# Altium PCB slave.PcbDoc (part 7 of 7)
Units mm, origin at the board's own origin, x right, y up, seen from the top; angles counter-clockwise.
Board outline 160 x 100 mm, 6 copper layers (Top, FUSED_VBAT-, Signals1, Signals2, SUPPLY, Bottom), stack 1.67 mm thick; 597 components, 381 nets, 1695 pads, 3028 vias.
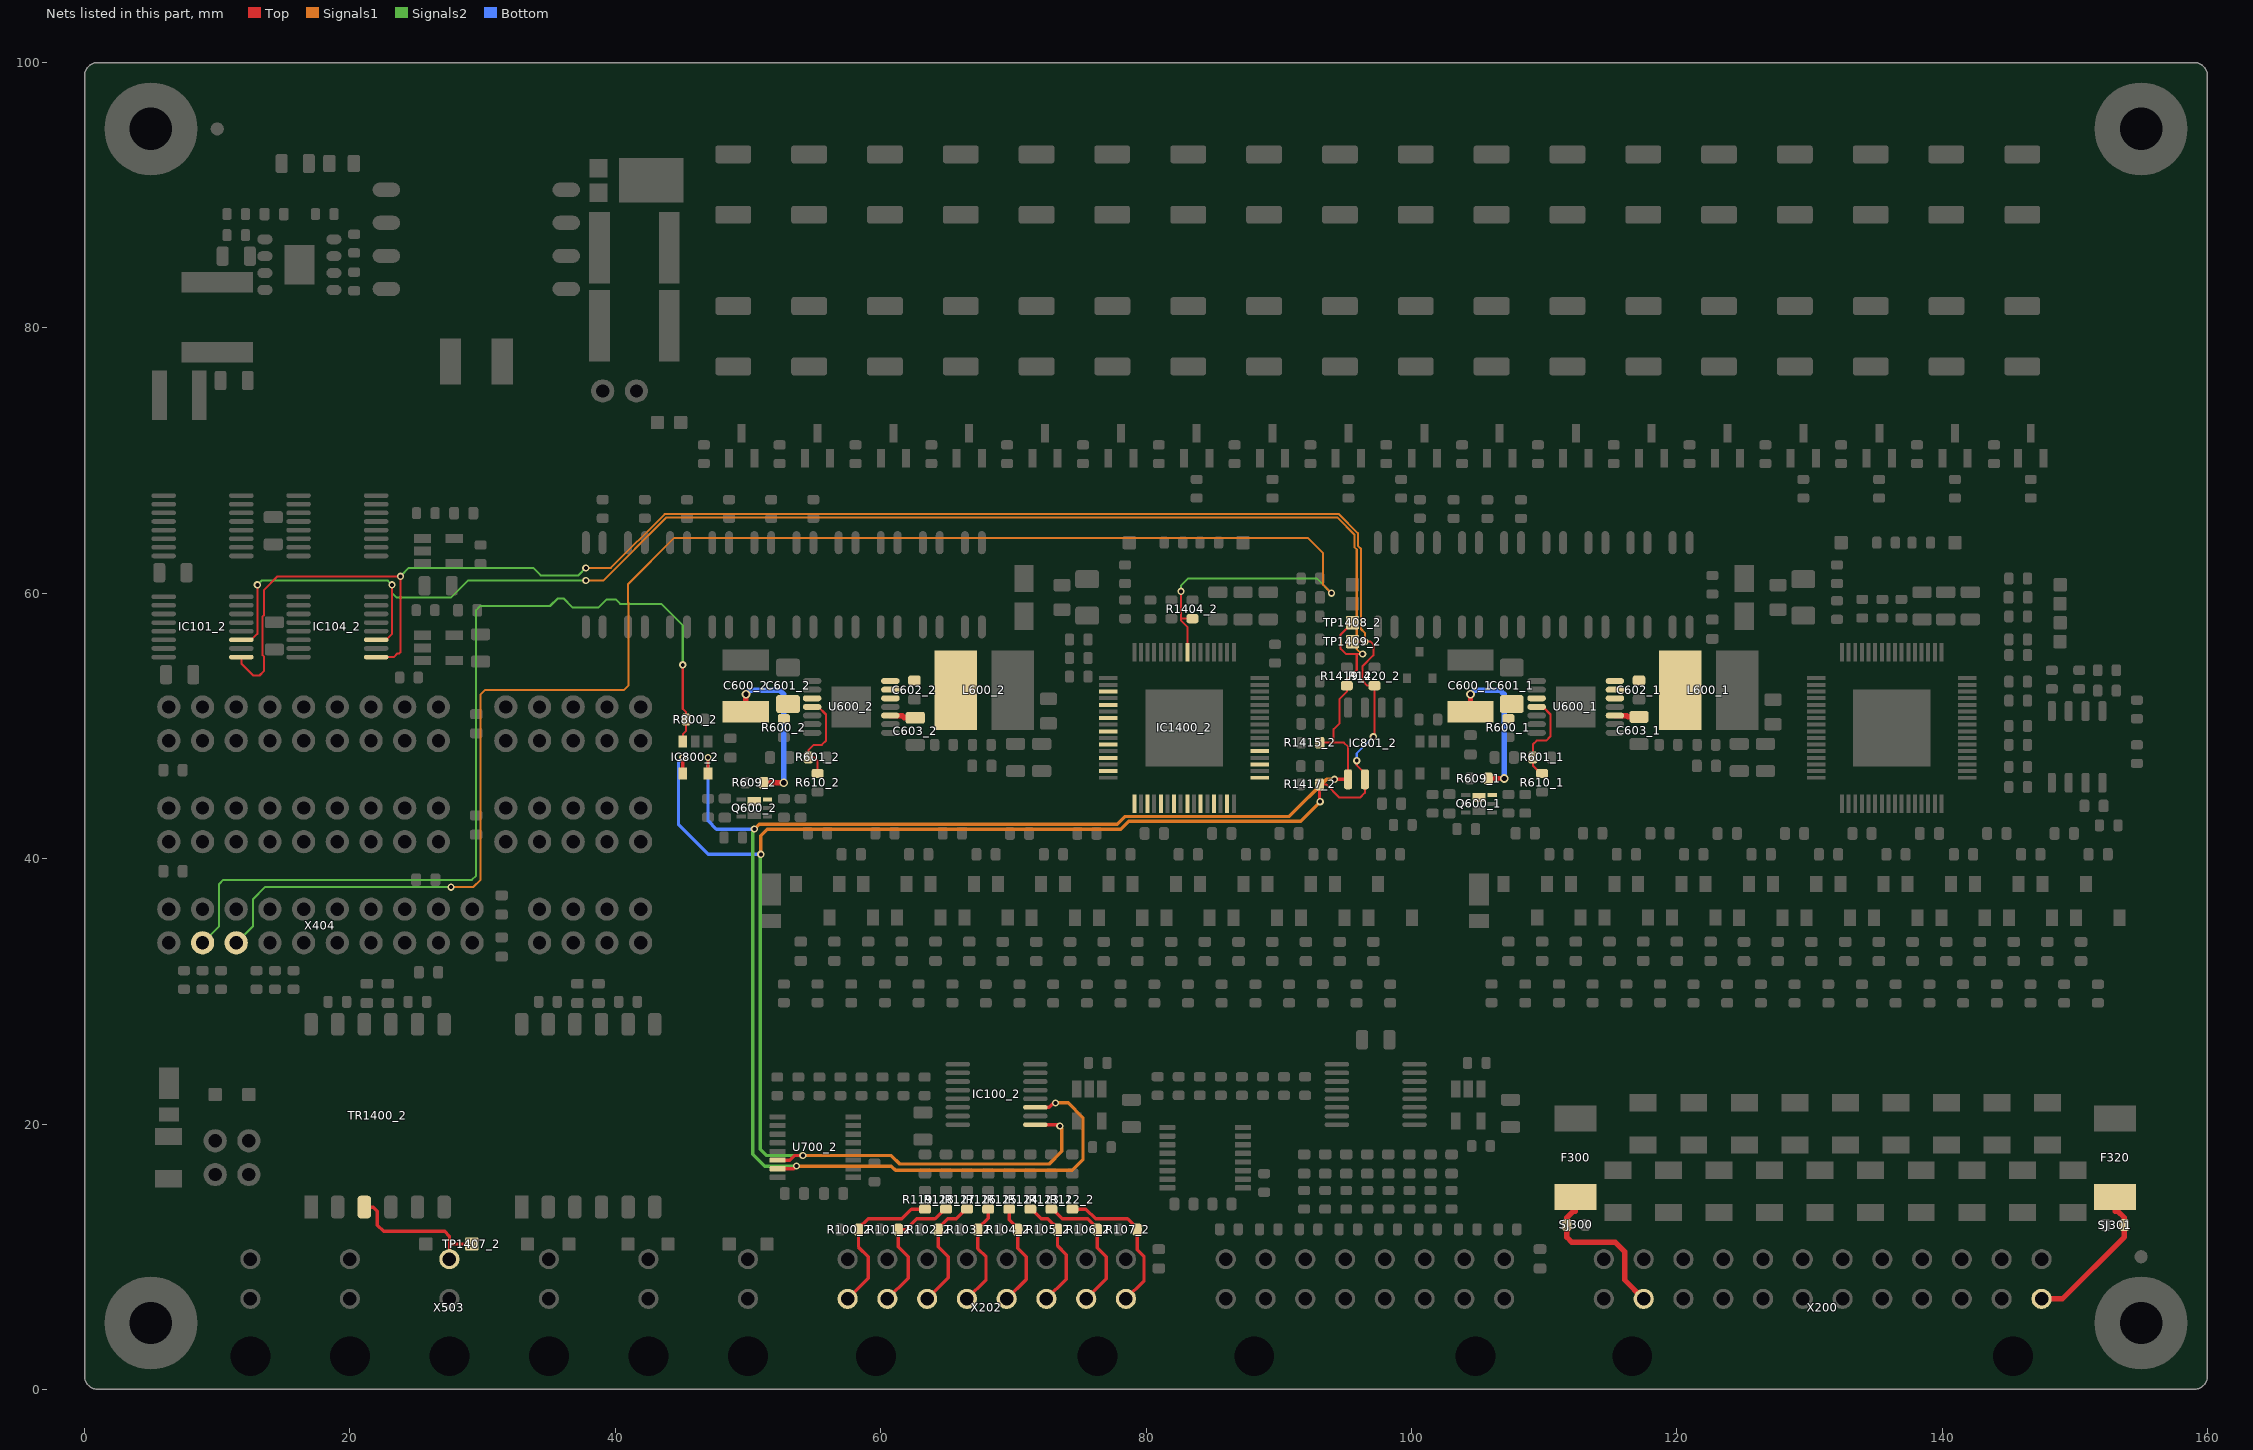
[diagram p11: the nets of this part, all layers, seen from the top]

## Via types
v1: diameter 0.55, hole 0.3, Top to Bottom, tented both sides, 2990 vias
v2: diameter 0.75, hole 0.5, Top to Bottom, tented both sides, 22 vias
v3: diameter 0.65, hole 0.4, Top to Bottom, tented both sides, 16 vias

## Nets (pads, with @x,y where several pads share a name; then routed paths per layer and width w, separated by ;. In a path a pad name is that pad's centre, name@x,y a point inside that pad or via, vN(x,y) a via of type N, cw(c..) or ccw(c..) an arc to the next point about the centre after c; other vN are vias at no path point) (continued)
SECONDARY-OUT-: TP1407_2.1 TR1400_2.3 X503.2 | length 11.4
  Top w0.254: TR1400_2.3@21.079,13.738 21.763,13.738 22.066,13.434 22.066,12.383 22.543,11.906 27.146,11.906 27.5,11.552 27.5,10.954 ; X503.2@27.5,9.815 27.5,10.954 ; TP1407_2.1@29.19,10.954 27.5,10.954
SECONDARY-S1: IC1400_2.37
SECONDARY-S2: IC1400_2.35
SECONDARY-S3: IC1400_2.33
SECONDARY-S4: IC1400_2.31
SECONDARY-S5: IC1400_2.29
SECONDARY-S6: IC1400_2.27
SECONDARY-S7: IC1400_2.25
SECONDARY-S8: IC1400_2.23
SECONDARY-S9: IC1400_2.21
SECONDARY-S10: IC1400_2.19
SECONDARY-S11: IC1400_2.17
SECONDARY-S12: IC1400_2.15
SECONDARY-S13: IC1400_2.13
SECONDARY-S14: IC1400_2.11
SECONDARY-S15: IC1400_2.9
SECONDARY-S16: IC1400_2.7
SECONDARY-S17: IC1400_2.5
SECONDARY-S18: IC1400_2.3
SECONDARY-SCL: IC100_2.1 IC101_2.1 IC104_2.1 IC800_2.4 IC801_2.6 R1417_2.1 R1420_2.1 TP1409_2.1 U700_2.14 | length 240.8
  Top w0.152: IC101_2.1@11.815,55.193 11.815,54.711 12.724,53.802 13.184,53.802 13.508,54.126 13.508,55.244 13.403,55.35 13.403,58.236 13.508,58.342 13.508,60.244 14.529,61.265 23.8,61.265 v1(23.812,61.277) 23.812,55.562 23.722,55.472 23.583,55.472 23.292,55.181 23.013,55.181 23.002,55.193 IC104_2.1@21.975,55.193 ; IC104_2.1@21.946,55.181 IC104_2.1@21.975,55.181 ; R1417_2.1@93.093,45.605 93.575,45.605 94.571,44.609 96.153,44.609 96.5,44.956 IC801_2.6@96.5,45.98 96.5,46.43 95.885,47.045 v1(95.885,47.38) ; R1417_2.1@93.129,45.548 R1417_2.1@93.143,45.561 ; TP1409_2.1@95.567,56.356 96.93,56.356 97.135,56.151 97.135,55.322 96.315,54.502 96.315,53.393 96.671,53.037 R1420_2.1@97.223,53.037 97.223,49.268 v1(97.135,49.18)
  Top w0.254: IC800_2.4@45.085,46.428 IC800_2.4@45.088,46.425 45.088,47.622 v1(45.085,47.625) ; U700_2.14@52.236,17.281 53.159,17.281 53.499,17.621 v1(54.134,17.621) ; IC100_2.1@71.664,19.95 73.395,19.95 v1(73.501,19.844) ; R1417_2.1@93.072,45.605 93.072,44.341 v1(93.122,44.291)
  Signals2 w0.152: v1(23.812,61.277) 24.447,61.912 33.823,61.912 34.378,61.358 37.228,61.358 v1(37.782,61.912)
  Signals2 w0.254: v1(50.97,40.322) 50.939,40.291 50.939,18.098 51.415,17.621 v1(54.134,17.621)
  Signals1 w0.152: v1(37.782,61.912) 39.671,61.912 43.718,65.959 94.545,65.959 95.966,64.539 95.966,63.588 96.203,63.351 96.203,57.309 96.5,57.011 v1(96.5,56.357)
  Signals1 w0.254: v1(50.97,40.322) 50.97,41.74 51.458,42.227 78.105,42.227 78.702,42.824 91.656,42.824 v1(93.122,44.291) ; v1(54.134,17.621) 60.801,17.621 61.436,16.986 72.707,16.986 73.66,17.939 73.66,19.685 v1(73.501,19.844)
  Bottom w0.152: v1(95.885,47.38) 95.885,47.942 97.122,49.18 v1(97.135,49.18)
  Bottom w0.254: v1(45.085,47.625) 44.767,47.307 44.767,42.545 46.99,40.322 v1(50.97,40.322)
SECONDARY-SDA: IC100_2.3 IC101_2.3 IC104_2.3 IC800_2.5 IC801_2.5 R1415_2.1 R1419_2.1 TP1408_2.1 U700_2.15 | length 238.5
  Top w0.152: IC101_2.3@11.786,56.502 IC101_2.3@11.815,56.502 ; IC101_2.3@11.815,56.493 12.565,56.493 13.018,56.945 v1(13.018,60.642) ; IC104_2.3@21.946,56.502 IC104_2.3@22.735,56.502 ; IC104_2.3@21.975,56.493 22.725,56.493 IC104_2.3@22.735,56.502 ; v1(23.177,60.642) 23.177,56.945 IC104_2.3@22.735,56.502 ; R1415_2.1@93.134,48.767 93.139,48.748 93.143,48.736 94.139,48.736 ; IC801_2.5@95.23,45.98 95.23,48.422 94.916,48.736 94.139,48.736 ; TP1408_2.1@95.567,57.785 94.675,56.892 94.675,55.82 95.068,55.427 95.885,55.427 ; v1(96.335,55.427) 95.885,55.427 ; 94.139,48.736 94.139,49.753 94.595,50.209 94.595,52.042 95.135,52.582 R1419_2.1@95.135,53.034 95.135,53.485 95.556,53.906 95.885,54.235 95.885,55.427
  Top w0.254: IC800_2.5@46.988,46.425 46.988,47.623 v1(46.99,47.625) ; U700_2.15@52.236,16.631 53.461,16.631 v1(53.657,16.828) ; IC100_2.3@71.664,21.25 72.69,21.25 73.03,21.59 v1(73.184,21.59) ; v1(94.212,45.98) IC801_2.5@95.23,45.98
  Signals2 w0.152: v1(13.018,60.642) 13.335,60.96 22.86,60.96 v1(23.177,60.642) 23.177,60.008 23.495,59.69 27.622,59.69 28.892,60.96 v1(37.782,60.96)
  Signals2 w0.254: v1(50.482,42.227) 50.365,42.11 50.365,17.719 51.256,16.828 v1(53.657,16.828)
  Signals1 w0.152: v1(37.782,60.96) 39.078,60.96 43.823,65.705 94.44,65.705 95.712,64.434 95.712,63.483 95.885,63.309 95.885,55.792 96.25,55.427 v1(96.335,55.427)
  Signals1 w0.254: v1(50.482,42.227) 50.838,42.583 51.458,42.583 77.826,42.583 78.422,43.18 90.805,43.18 93.605,45.98 v1(94.212,45.98) ; v1(53.657,16.828) 60.801,16.828 61.119,16.51 74.454,16.51 75.248,17.304 75.248,20.479 74.136,21.59 v1(73.184,21.59)
  Bottom w0.254: v1(46.99,47.625) 46.99,42.862 47.625,42.227 v1(50.482,42.227)
SECONDARY-T-SENSOR_0: R107_2.1 R112_2.2 X202.1 | length 11.6
  Top w0.254: R112_2.2@74.454,13.588 75.471,13.588 76.2,12.859 78.608,12.859 79.332,12.135 R107_2.1@79.332,12.035 79.332,10.521 79.851,10.001 79.851,8.179 X202.1@78.49,6.818
SECONDARY-T-SENSOR_1: R106_2.1 R113_2.2 X202.2 | length 10.3
  Top w0.254: R113_2.2@72.866,13.588 72.966,13.588 73.695,12.859 75.608,12.859 76.332,12.135 R106_2.1@76.332,12.035 76.332,10.663 76.994,10.001 76.994,8.319 X202.2@75.493,6.818
SECONDARY-T-SENSOR_2: R105_2.1 R114_2.2 X202.3 | length 8.9
  Top w0.254: R114_2.2@71.279,13.588 71.379,13.588 72.108,12.859 72.608,12.859 73.332,12.135 R105_2.1@73.332,12.035 73.332,10.806 73.977,10.16 73.977,8.299 X202.3@72.496,6.818
SECONDARY-T-SENSOR_3: R104_2.1 R115_2.2 X202.4 | length 7.9
  Top w0.254: X202.4@69.499,6.818 70.961,8.28 70.961,10.001 70.332,10.631 R104_2.1@70.332,12.035 70.332,12.135 69.691,12.775 R115_2.2@69.691,13.588
SECONDARY-T-SENSOR_4: R103_2.1 R116_2.2 X202.5 | length 7.9
  Top w0.254: X202.5@66.501,6.818 67.945,8.262 67.945,10.001 67.332,10.615 R103_2.1@67.332,12.035 67.332,12.135 68.104,12.907 R116_2.2@68.104,13.588
SECONDARY-T-SENSOR_5: R102_2.1 R117_2.2 X202.6 | length 9.1
  Top w0.254: X202.6@63.504,6.818 65.087,8.401 65.087,10.001 64.331,10.757 R102_2.1@64.331,12.035 64.331,12.135 65.055,12.859 65.687,12.859 66.416,13.588 R117_2.2@66.516,13.588
SECONDARY-T-SENSOR_6: R101_2.1 R118_2.2 X202.7 | length 10.4
  Top w0.254: X202.7@60.507,6.818 62.071,8.382 62.071,10.001 61.331,10.741 R101_2.1@61.331,12.035 61.883,12.035 62.706,12.859 64.1,12.859 64.829,13.588 R118_2.2@64.929,13.588
SECONDARY-T-SENSOR_7: R100_2.1 R119_2.2 X202.8 | length 11.9
  Top w0.254: X202.8@57.51,6.818 59.055,8.363 59.055,10.001 58.331,10.725 R100_2.1@58.331,12.035 58.331,12.135 59.055,12.859 61.595,12.859 62.324,13.588 R119_2.2@63.341,13.588
SECONDARY-TEMP-ALERT: IC800_2.3 R800_2.1 X404.18 | length 70.8
  Top w0.152: v1(45.085,54.61) 45.085,51.286 45.337,51.033 R800_2.1@45.337,50.482 45.337,49.627 45.088,49.377 IC800_2.3@45.088,48.825
  Signals2 w0.152: X404.18@8.89,33.655 10.14,34.905 10.14,38.088 10.457,38.405 29.19,38.405 29.507,38.723 29.507,58.725 29.825,59.043 35.081,59.043 35.648,59.609 36.107,59.609 36.771,58.945 38.752,58.945 39.353,59.546 40.022,59.546 40.369,59.199 43.476,59.199 45.085,57.59 v1(45.085,54.61)
SECONDARY-WDT: IC1400_2.56 R1404_2.1 X404.16 | length 130.3
  Top w0.152: v1(82.631,60.145) 82.631,58.102 ; IC1400_2.56@83.117,55.598 83.117,57.474 82.631,57.96 82.631,58.102 ; R1404_2.1@83.502,58.088 82.646,58.088 82.631,58.102
  Signals2 w0.152: X404.16@11.43,33.655 12.7,34.925 12.7,36.957 13.589,37.846 v1(27.618,37.846) ; v1(82.631,60.145) 82.631,60.565 83.185,61.119 92.869,61.119 v1(93.98,60.008)
  Signals1 w0.152: v1(27.618,37.846) 29.273,37.846 29.845,38.417 29.845,52.387 30.162,52.705 40.64,52.705 41.004,53.069 41.004,59.283 40.957,59.329 40.957,60.684 44.455,64.181 92.197,64.181 93.345,63.033 93.345,60.642 v1(93.98,60.008)
SHDN_1: R601_1.1 R610_1.1 U600_1.4 | length 7.1
  Top w0.152: U600_1.4@109.445,51.435 109.92,51.435 110.49,50.865 110.49,49.212 110.172,48.895 109.445,48.895 109.155,48.605 R601_1.1@109.155,47.625 109.155,47.02 109.755,46.42 R610_1.1@109.855,46.42
SHDN_2: R601_2.1 R610_2.1 U600_2.4 | length 7.2
  Top w0.152: U600_2.4@54.835,51.435 55.31,51.435 55.88,50.865 55.88,48.895 55.562,48.578 54.946,48.578 54.545,48.177 R601_2.1@54.545,47.625 54.997,47.625 55.245,47.377 R610_2.1@55.245,46.42
SW_1: C602_1.1 L600_1.1 U600_1.12 U600_1.13 U600_1.14
SW_2: C602_2.1 L600_2.1 U600_2.12 U600_2.13 U600_2.14
VBAT+: F300.1 SJ300.1 X200.11 | length 12.4
  Top w0.406: F300.1@112.375,14.5 112.375,13.418 112.187,13.418 111.715,12.947 SJ300.1@111.715,12.395 111.715,11.465 112.08,11.1 115.353,11.1 116.07,10.384 116.07,8.261 X200.11@117.513,6.818
VBAT-: F320.1 SJ301.2 X200.1 | length 11.6
  Top w0.406: X200.1@147.497,6.818 149.058,6.818 153.735,11.495 SJ301.2@153.735,12.383 153.735,12.934 153.238,13.431 153.035,13.431 F320.1@153.035,14.513
VCC_1: C603_1.2 U600_1.10 | length 1.9
  Top w0.406: U600_1.10@115.345,50.785 116.228,50.785 116.331,50.682 C603_1.2@117.157,50.682
VCC_2: C603_2.2 U600_2.10 | length 1.9
  Top w0.406: U600_2.10@60.735,50.785 61.618,50.785 61.784,50.619 C603_2.2@62.611,50.619
VIN_1: C600_1.2 C601_1.2 Q600_1.3 Q600_1.8 R600_1.2 R609_1.1 U600_1.3 | length 11.7
  Top w0.406: C600_1.2@104.457,51.073 v3(104.457,52.387) ; R609_1.1@105.793,46.038 v3(106.998,46.038)
  Bottom w0.406: v3(104.457,52.387) 104.775,52.705 106.68,52.705 106.998,52.387 v3(106.998,46.038)
VIN_2: C600_2.2 C601_2.2 Q600_2.3 Q600_2.8 R600_2.2 R609_2.1 U600_2.3 | length 12.6
  Top w0.406: C600_2.2@49.847,51.073 v3(49.847,52.387) ; R609_2.1@51.183,45.72 v3(52.705,45.72)
  Bottom w0.406: v3(49.847,52.387) 50.165,52.705 52.387,52.705 52.705,52.387 v3(52.705,45.72)
pads on no net: Designator5.Hole_3.2 Designator6.Hole_3.2 Designator7.Hole_3.2 Designator8.Hole_3.2 Designator11.0 Designator12.0 IC801_1.1 IC801_1.2 IC801_2.1 IC801_2.2 IC1400_1.53 IC1400_1.54 IC1400_2.53 IC1400_2.54 TR1400_1.2 TR1400_1.5 TR1400_2.2 TR1400_2.5 U700_1.13 U700_2.13 X200. X200.12 X200.23 X200.24 X201. X202. X500. X501. X502. X503. X1001. X1002.

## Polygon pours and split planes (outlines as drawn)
+5.0V_VREG_1 on SUPPLY "SUPPLY-+5.0V_VREG_1" (solid, pour order 811): 5.08,59.69 32.703,59.69 32.703,53.34 44.767,53.34 44.767,45.72 5.08,45.72
+5.0V_VREG_1 on SUPPLY "Polygon_1_Net_+5.0V_VREG_1" (solid, remove dead copper, pour order 222): 5.08,32.067 17.145,32.067 52.07,32.067 52.07,13.97 55.88,13.97 55.88,0 79.375,0 79.375,31.75 100.647,31.75 100.647,63.817 48.895,63.817 48.895,34.608 5.08,34.608
+5.0V_VREG_0 on SUPPLY "Polygon_1_Net_+5.0V_VREG_0" (solid, remove dead copper, pour order 223): 17 vertices, not listed, extent 5.08,-0.185 160.384,69.27
NetC900_2 on Top "Polygon_1_Net_N$74" (solid, remove dead copper, pour order 779): 10.795,76.835 10.795,72.866 7.938,72.866 7.937,76.835
NetC902_2 on Top "Polygon_1_Net_N$1254" (solid, remove dead copper, pour order 761): 21 vertices, not listed, extent 4.763,72.866 23.812,93.345
EXT_DC_IN- on Top "Polygon_1_Net_EXT_DC_IN-" (solid, remove dead copper, pour order 753): 14.922,83.502 14.922,89.218 17.399,89.218 17.399,79.692 28.575,79.692 28.575,75.248 11.271,75.247 11.271,77.152 7.144,77.152 7.144,80.804 13.018,80.804 13.018,83.502
FUSED_VBAT- on Top "Polygon_2_Net_FUSED_VBAT-" (solid, pour order 759): 39.688,88.9 39.688,73.66 30.48,73.66 30.48,79.375 34.925,79.375 34.925,83.82 38.1,83.82 38.1,88.9
EXT_DC_ISO+ on Top "Polygon_1_Net_EXT_DC_ISO+" (solid, pour order 755): 45.402,93.662 45.402,73.66 40.957,73.66 40.957,89.535 40.322,89.535 40.322,93.662
+5.0V_VREG_1 on Top "Top-+5.0V_VREG_1" (solid, pour order 797): 67.945,55.88 67.945,46.355 68.897,46.355 68.897,49.53 70.802,49.53 70.802,51.435 73.66,51.435 73.66,55.88
EXT_DC_ISO+ on Top "Top-EXT_DC_ISO+ 1" (solid, pour order 821): 46.37,45.085 49.212,45.085 49.212,46.355 50.165,46.355 50.165,45.085 49.847,45.085 49.847,44.133 46.37,44.133
VIN_2 on Top "Top-VIN_2" (solid, pour order 823): 49.939,44.767 50.482,44.767 50.482,46.355 52.07,46.355 52.07,44.132 51.117,44.133 51.117,43.815 49.939,43.815
VIN_2 on Top "Top-EXT_DC_ISO+" (solid, pour order 789): 47.625,52.387 55.562,52.387 55.562,51.752 53.657,51.752 53.657,50.165 47.625,50.165
FUSED_VBAT- on Top "Top-FUSED_VBAT-" (solid, pour order 787): 18 vertices, not listed, extent 47.625,44.767 73.025,55.88
EXT_DC_ISO+ on Top "Top-EXT_DC_ISO+ 2" (solid, pour order 819): 100.98,45.402 103.822,45.402 103.822,46.672 104.775,46.672 104.775,45.402 104.457,45.402 104.457,44.45 100.98,44.45
VIN_1 on Top "Top-VIN_1" (solid, pour order 817): 104.549,45.085 105.093,45.085 105.093,46.672 106.68,46.672 106.68,44.45 105.727,44.45 105.727,44.133 104.549,44.133
VIN_1 on Top "Top-EXT_DC_ISO+" (solid, pour order 799): 102.235,52.388 110.172,52.387 110.172,51.752 108.267,51.752 108.267,50.165 102.235,50.165 102.235,51.752
FUSED_VBAT- on Top "Top-FUSED_VBAT-" (solid, pour order 807): 18 vertices, not listed, extent 102.235,44.767 127.635,55.88
NetC605_1_2 on Top "Top-NetC1505_2_2" (solid, pour order 803): 124.46,49.212 125.73,49.212 125.73,50.8 128.27,50.8 128.27,48.26 124.46,48.26
+5.0V_VREG_0 on Top "Top-+5.0V_VREG_1" (solid, pour order 801): 122.555,55.88 122.555,46.355 123.507,46.355 123.507,49.53 125.412,49.53 125.412,51.435 128.27,51.435 128.27,55.88
SW_2 on Top "Top-SW_2" (solid, pour order 815): 60.008,53.975 63.817,53.975 63.817,55.88 66.675,55.88 66.675,49.53 63.817,49.53 63.817,52.705 61.595,52.705 61.595,51.752 60.008,51.752
SW_1 on Top "Top-SW_2" (solid, pour order 805): 114.617,53.975 118.427,53.975 118.427,55.88 121.285,55.88 121.285,49.53 118.427,49.53 118.427,52.705 116.205,52.705 116.205,51.752 114.617,51.752
CELL_FEEDBACK.CELL17_FEEDBACK+ on Top "Polygon_1_Net_CELL0_FEEDBACK+" (solid, pour order 417): 51.435,71.755 46.355,71.755 46.355,78.74 51.435,78.74
NetC605_2_2 on Top "Top-NetC1505_2_2" (solid, pour order 793): 69.85,49.212 71.12,49.212 71.12,50.8 73.66,50.8 73.66,48.26 69.85,48.26
NetIC900_5 on Top "Polygon_1_Net_N$80" (solid, remove dead copper, pour order 763): 26.352,81.597 26.352,93.345 19.685,93.345 19.685,91.44 24.447,91.44 24.447,86.36 21.59,86.36 21.59,83.502 18.098,83.502 18.097,81.597
NetD901_2 on Top "Polygon_1_Net_N$84" (solid, remove dead copper, pour order 757): 39.37,93.662 39.37,89.535 34.925,89.535 34.925,93.662
NetC905_1 on Top "Polygon_1_Net_N$92" (solid, remove dead copper, pour order 751): 16.192,93.345 16.192,91.44 19.05,91.44 19.05,93.345
NetTR900_6 on Top "Polygon_1_Net_N$74" (solid, remove dead copper, pour order 745): 37.465,88.9 37.465,84.455 34.925,84.455 34.925,88.9
CELL_FEEDBACK.CELL0_FEEDBACK+ on Top "Polygon_1_Net_FUSED_CELL_0-" (solid, pour order 193): 148.59,91.44 143.51,91.44 143.51,98.425 148.59,98.425
FUSED_CELL.CELL_12+ on Top "Polygon_1_Net_N$4" (solid, pour order 375): 74.295,90.17 74.295,80.01 69.215,80.01 69.215,90.17
CELL_FEEDBACK.CELL1_FEEDBACK+ on Top "Polygon_1_Net_CELL0_FEEDBACK+" (solid, pour order 385): 142.875,71.755 137.795,71.755 137.795,78.74 142.875,78.74
CELL_FEEDBACK.CELL0_FEEDBACK+ on Top "Polygon_1_Net_CELL0_FEEDBACK+" (solid, pour order 185): 148.59,71.755 143.51,71.755 143.51,78.74 148.59,78.74
CELL_FEEDBACK.CELL16_FEEDBACK+ on Top "Polygon_1_Net_CELL0_FEEDBACK+" (solid, pour order 415): 57.15,71.755 52.07,71.755 52.07,78.74 57.15,78.74
FUSED_CELL.CELL_0- on Top "Polygon_1_Net_N$4" (solid, pour order 214): 148.59,90.17 148.59,80.01 143.51,80.01 143.51,90.17
CELL_FEEDBACK.CELL13_FEEDBACK+ on Top "Polygon_1_Net_CELL0_FEEDBACK+" (solid, pour order 409): 74.295,71.755 69.215,71.755 69.215,78.74 74.295,78.74
CELL_FEEDBACK.CELL14_FEEDBACK+ on Top "Polygon_1_Net_CELL0_FEEDBACK+" (solid, pour order 411): 68.58,71.755 63.5,71.755 63.5,78.74 68.58,78.74
CELL_FEEDBACK.CELL12_FEEDBACK+ on Top "Polygon_1_Net_CELL0_FEEDBACK+" (solid, pour order 407): 80.01,71.755 74.93,71.755 74.93,78.74 80.01,78.74
CELL_FEEDBACK.CELL11_FEEDBACK+ on Top "Polygon_1_Net_CELL0_FEEDBACK+" (solid, pour order 405): 85.725,71.755 80.645,71.755 80.645,78.74 85.725,78.74
CELL_FEEDBACK.CELL9_FEEDBACK+ on Top "Polygon_1_Net_CELL0_FEEDBACK+" (solid, pour order 401): 97.155,71.755 92.075,71.755 92.075,78.74 97.155,78.74
CELL_FEEDBACK.CELL8_FEEDBACK+ on Top "Polygon_1_Net_CELL0_FEEDBACK+" (solid, pour order 399): 102.873,71.755 97.793,71.755 97.793,78.74 102.873,78.74
CELL_FEEDBACK.CELL7_FEEDBACK+ on Top "Polygon_1_Net_CELL0_FEEDBACK+" (solid, pour order 397): 108.585,71.755 103.505,71.755 103.505,78.74 108.585,78.74
CELL_FEEDBACK.CELL6_FEEDBACK+ on Top "Polygon_1_Net_CELL0_FEEDBACK+" (solid, pour order 395): 114.303,71.755 109.223,71.755 109.223,78.74 114.303,78.74
CELL_FEEDBACK.CELL5_FEEDBACK+ on Top "Polygon_1_Net_CELL0_FEEDBACK+" (solid, pour order 393): 120.015,71.755 114.935,71.755 114.935,78.74 120.015,78.74
CELL_FEEDBACK.CELL4_FEEDBACK+ on Top "Polygon_1_Net_CELL0_FEEDBACK+" (solid, pour order 391): 125.73,71.755 120.65,71.755 120.65,78.74 125.73,78.74
CELL_FEEDBACK.CELL3_FEEDBACK+ on Top "Polygon_1_Net_CELL0_FEEDBACK+" (solid, pour order 389): 131.445,71.755 126.365,71.755 126.365,78.74 131.445,78.74
CELL_FEEDBACK.CELL2_FEEDBACK+ on Top "Polygon_1_Net_CELL0_FEEDBACK+" (solid, pour order 387): 137.16,71.755 132.08,71.755 132.08,78.74 137.16,78.74
CELL_FEEDBACK.CELL15_FEEDBACK+ on Top "Polygon_1_Net_CELL0_FEEDBACK+" (solid, pour order 413): 62.865,71.755 57.785,71.755 57.785,78.74 62.865,78.74
CELL_FEEDBACK.CELL10_FEEDBACK+ on Top "Polygon_1_Net_CELL0_FEEDBACK+" (solid, pour order 403): 91.44,71.755 86.36,71.755 86.36,78.74 91.44,78.74
FUSED_CELL.CELL_16+ on Top "Polygon_1_Net_N$4" (solid, pour order 383): 51.435,90.17 51.435,80.01 46.355,80.01 46.355,90.17
FUSED_CELL.CELL_15+ on Top "Polygon_1_Net_N$4" (solid, pour order 381): 57.15,90.17 57.15,80.01 52.07,80.01 52.07,90.17
FUSED_CELL.CELL_14+ on Top "Polygon_1_Net_N$4" (solid, pour order 379): 62.865,90.17 62.865,80.01 57.785,80.01 57.785,90.17
FUSED_CELL.CELL_13+ on Top "Polygon_1_Net_N$4" (solid, pour order 377): 68.58,90.17 68.58,80.01 63.5,80.01 63.5,90.17
FUSED_CELL.CELL_11+ on Top "Polygon_1_Net_N$4" (solid, pour order 373): 80.01,90.17 80.01,80.01 74.93,80.01 74.93,90.17
FUSED_CELL.CELL_10+ on Top "Polygon_1_Net_N$4" (solid, pour order 371): 85.725,90.17 85.725,80.01 80.645,80.01 80.645,90.17
FUSED_CELL.CELL_9+ on Top "Polygon_1_Net_N$4" (solid, pour order 369): 91.44,90.17 91.44,80.01 86.36,80.01 86.36,90.17
FUSED_CELL.CELL_8+ on Top "Polygon_1_Net_N$4" (solid, pour order 367): 97.155,90.17 97.155,80.01 92.075,80.01 92.075,90.17
FUSED_CELL.CELL_7+ on Top "Polygon_1_Net_N$4" (solid, pour order 365): 102.87,90.17 102.87,80.01 97.79,80.01 97.79,90.17
FUSED_CELL.CELL_6+ on Top "Polygon_1_Net_N$4" (solid, pour order 363): 108.585,90.17 108.585,80.01 103.505,80.01 103.505,90.17
FUSED_CELL.CELL_5+ on Top "Polygon_1_Net_N$4" (solid, pour order 361): 114.303,90.17 114.303,80.01 109.223,80.01 109.223,90.17
FUSED_CELL.CELL_4+ on Top "Polygon_1_Net_N$4" (solid, pour order 359): 120.015,90.17 120.015,80.01 114.935,80.01 114.935,90.17
FUSED_CELL.CELL_3+ on Top "Polygon_1_Net_N$4" (solid, pour order 357): 125.73,90.17 125.73,80.01 120.65,80.01 120.65,90.17
FUSED_CELL.CELL_2+ on Top "Polygon_1_Net_N$4" (solid, pour order 355): 131.445,90.17 131.445,80.01 126.365,80.01 126.365,90.17
FUSED_CELL.CELL_1+ on Top "Polygon_1_Net_N$4" (solid, pour order 353): 137.16,90.17 137.16,80.01 132.08,80.01 132.08,90.17
FUSED_CELL.CELL_0+ on Top "Polygon_1_Net_N$4" (solid, pour order 351): 142.875,90.17 142.875,80.01 137.795,80.01 137.795,90.17
CELL_FEEDBACK.CELL17_FEEDBACK+ on Top "Polygon_1_Net_FUSED_CELL_0-" (solid, pour order 349): 51.435,91.44 46.355,91.44 46.355,98.425 51.435,98.425
CELL_FEEDBACK.CELL16_FEEDBACK+ on Top "Polygon_1_Net_FUSED_CELL_0-" (solid, pour order 347): 57.15,91.44 52.07,91.44 52.07,98.425 57.15,98.425
CELL_FEEDBACK.CELL15_FEEDBACK+ on Top "Polygon_1_Net_FUSED_CELL_0-" (solid, pour order 345): 62.865,91.44 57.785,91.44 57.785,98.425 62.865,98.425
CELL_FEEDBACK.CELL14_FEEDBACK+ on Top "Polygon_1_Net_FUSED_CELL_0-" (solid, pour order 343): 68.58,91.44 63.5,91.44 63.5,98.425 68.58,98.425
CELL_FEEDBACK.CELL13_FEEDBACK+ on Top "Polygon_1_Net_FUSED_CELL_0-" (solid, pour order 341): 74.295,91.44 69.215,91.44 69.215,98.425 74.295,98.425
CELL_FEEDBACK.CELL12_FEEDBACK+ on Top "Polygon_1_Net_FUSED_CELL_0-" (solid, pour order 339): 80.01,91.44 74.93,91.44 74.93,98.425 80.01,98.425
CELL_FEEDBACK.CELL11_FEEDBACK+ on Top "Polygon_1_Net_FUSED_CELL_0-" (solid, pour order 337): 85.725,91.44 80.645,91.44 80.645,98.425 85.725,98.425
CELL_FEEDBACK.CELL10_FEEDBACK+ on Top "Polygon_1_Net_FUSED_CELL_0-" (solid, pour order 335): 91.44,91.44 86.36,91.44 86.36,98.425 91.44,98.425
CELL_FEEDBACK.CELL9_FEEDBACK+ on Top "Polygon_1_Net_FUSED_CELL_0-" (solid, pour order 333): 97.155,91.44 92.075,91.44 92.075,98.425 97.155,98.425
CELL_FEEDBACK.CELL8_FEEDBACK+ on Top "Polygon_1_Net_FUSED_CELL_0-" (solid, pour order 331): 102.87,91.44 97.79,91.44 97.79,98.425 102.87,98.425
CELL_FEEDBACK.CELL7_FEEDBACK+ on Top "Polygon_1_Net_FUSED_CELL_0-" (solid, pour order 329): 108.585,91.44 103.505,91.44 103.505,98.425 108.585,98.425
CELL_FEEDBACK.CELL6_FEEDBACK+ on Top "Polygon_1_Net_FUSED_CELL_0-" (solid, pour order 327): 114.3,91.44 109.22,91.44 109.22,98.425 114.3,98.425
CELL_FEEDBACK.CELL5_FEEDBACK+ on Top "Polygon_1_Net_FUSED_CELL_0-" (solid, pour order 325): 120.015,91.44 114.935,91.44 114.935,98.425 120.015,98.425
CELL_FEEDBACK.CELL4_FEEDBACK+ on Top "Polygon_1_Net_FUSED_CELL_0-" (solid, pour order 323): 125.73,91.44 120.65,91.44 120.65,98.425 125.73,98.425
CELL_FEEDBACK.CELL3_FEEDBACK+ on Top "Polygon_1_Net_FUSED_CELL_0-" (solid, pour order 321): 131.445,91.44 126.365,91.44 126.365,98.425 131.445,98.425
CELL_FEEDBACK.CELL2_FEEDBACK+ on Top "Polygon_1_Net_FUSED_CELL_0-" (solid, pour order 319): 137.16,91.44 132.08,91.44 132.08,98.425 137.16,98.425
CELL_FEEDBACK.CELL1_FEEDBACK+ on Top "Polygon_1_Net_FUSED_CELL_0-" (solid, pour order 317): 142.875,91.44 137.795,91.44 137.795,98.425 142.875,98.425
no net on Top Overlay "Polygon_1_NoNet" (solid): 159.385,58.737 152.4,58.738 152.4,80.486 159.385,80.486
no net on Top Overlay "Polygon_22_NoNet" (solid): 105 vertices, not listed, extent 23.444,67.792 40.588,73.328
no net on Top Overlay "Polygon_23_NoNet" (solid): 75 vertices, not listed, extent 36.787,69.287 38.535,71.841
no net on Top Overlay "Polygon_24_NoNet" (solid): 33 vertices, not listed, extent 34.064,69.294 36.283,71.835
no net on Top Overlay "Polygon_25_NoNet" (solid): 69 vertices, not listed, extent 31.768,69.308 33.548,71.82
no net on Top Overlay "Polygon_26_NoNet" (solid): 53 vertices, not listed, extent 28.694,69.284 30.924,71.507
no net on Top Overlay "Polygon_27_NoNet" (solid): 60 vertices, not listed, extent 26.681,69.28 28.703,71.507
no net on Top Overlay "Polygon_28_NoNet" (solid): 61 vertices, not listed, extent 24.709,68.508 26.937,72.326
no net on Top Overlay "Polygon_42_NoNet" (solid): 33 vertices, not listed, extent 1.338,53.42 1.87,53.948
no net on Top Overlay "Polygon_41_NoNet" (solid): 17 vertices, not listed, extent 1.941,53.184 3.698,54.184
no net on Top Overlay "Polygon_40_NoNet" (solid): 133 vertices, not listed, extent 0.698,51.865 4.337,55.503
no net on Top Overlay "Polygon_39_NoNet" (solid): 59 vertices, not listed, extent 1.945,49.506 3.092,50.55
no net on Top Overlay "Polygon_38_NoNet" (solid): 58 vertices, not listed, extent 1.945,48.461 3.092,49.505
no net on Top Overlay "Polygon_37_NoNet" (solid): 134 vertices, not listed, extent 0.7,47.684 4.337,51.322
FUSED_VBAT- on Bottom "Polygon_2_Net_FUSED_VBAT-" (solid, remove dead copper, pour order 279): 75.248,42.227 75.248,57.468 90.487,57.468 90.487,42.227
FUSED_VBAT- on Bottom "Polygon_3_Net_FUSED_VBAT-" (solid, remove dead copper, pour order 278): 128.588,42.227 128.588,57.468 143.827,57.468 143.827,42.227
EXT_DC_IN- on Bottom "Polygon_2_Net_EXT_DC_IN-" (solid, pour order 773): 26.352,75.248 26.352,93.345 14.287,93.345 14.287,91.122 6.35,91.123 6.35,87.312 4.763,87.312 4.763,75.248
EXT_DC_ISO+ on Bottom "Polygon_6_Net_EXT_DC_ISO+" (solid, remove dead copper, pour order 771): 45.402,93.662 45.402,73.66 40.957,73.66 40.957,89.217 40.005,89.218 40.005,93.662
FUSED_VBAT- on Bottom "Polygon_3_Net_FUSED_VBAT-" (solid, pour order 769): 39.687,88.9 39.687,73.66 30.48,73.66 30.48,79.375 34.925,79.375 34.925,83.82 37.889,83.82 37.889,88.9
NetD901_2 on Bottom "Polygon_2_Net_N$84" (solid, pour order 767): 39.688,93.662 39.688,89.218 34.925,89.217 34.925,93.662
NetTR900_6 on Bottom "Polygon_2_Net_N$74" (solid, pour order 765): 37.465,88.9 37.465,84.455 34.925,84.455 34.925,88.9
CELL_FEEDBACK.CELL0_FEEDBACK+ on Bottom "Polygon_1_Net_FUSED_CELL_0-" (solid, pour order 739): 148.59,91.44 143.51,91.44 143.51,98.425 148.59,98.425
FUSED_CELL.CELL_12+ on Bottom "Polygon_1_Net_N$4" (solid, pour order 679): 74.295,90.17 74.295,80.01 69.215,80.01 69.215,90.17
FUSED_CELL.CELL_0- on Bottom "Polygon_1_Net_N$4" (solid, pour order 741): 148.59,90.17 148.59,80.01 143.51,80.01 143.51,90.17
CELL_FEEDBACK.CELL0_FEEDBACK+ on Bottom "Polygon_1_Net_CELL0_FEEDBACK+" (solid, pour order 743): 148.59,71.755 143.51,71.755 143.51,78.74 148.59,78.74
CELL_FEEDBACK.CELL1_FEEDBACK+ on Bottom "Polygon_1_Net_FUSED_CELL_0-" (solid, pour order 737): 142.875,91.44 137.795,91.44 137.795,98.425 142.875,98.425
CELL_FEEDBACK.CELL2_FEEDBACK+ on Bottom "Polygon_1_Net_FUSED_CELL_0-" (solid, pour order 735): 137.16,91.44 132.08,91.44 132.08,98.425 137.16,98.425
CELL_FEEDBACK.CELL3_FEEDBACK+ on Bottom "Polygon_1_Net_FUSED_CELL_0-" (solid, pour order 733): 131.445,91.44 126.365,91.44 126.365,98.425 131.445,98.425
CELL_FEEDBACK.CELL4_FEEDBACK+ on Bottom "Polygon_1_Net_FUSED_CELL_0-" (solid, pour order 731): 125.73,91.44 120.65,91.44 120.65,98.425 125.73,98.425
CELL_FEEDBACK.CELL5_FEEDBACK+ on Bottom "Polygon_1_Net_FUSED_CELL_0-" (solid, pour order 729): 120.015,91.44 114.935,91.44 114.935,98.425 120.015,98.425
CELL_FEEDBACK.CELL6_FEEDBACK+ on Bottom "Polygon_1_Net_FUSED_CELL_0-" (solid, pour order 727): 114.3,91.44 109.22,91.44 109.22,98.425 114.3,98.425
CELL_FEEDBACK.CELL7_FEEDBACK+ on Bottom "Polygon_1_Net_FUSED_CELL_0-" (solid, pour order 725): 108.585,91.44 103.505,91.44 103.505,98.425 108.585,98.425
CELL_FEEDBACK.CELL8_FEEDBACK+ on Bottom "Polygon_1_Net_FUSED_CELL_0-" (solid, pour order 723): 102.87,91.44 97.79,91.44 97.79,98.425 102.87,98.425
CELL_FEEDBACK.CELL9_FEEDBACK+ on Bottom "Polygon_1_Net_FUSED_CELL_0-" (solid, pour order 721): 97.155,91.44 92.075,91.44 92.075,98.425 97.155,98.425
CELL_FEEDBACK.CELL10_FEEDBACK+ on Bottom "Polygon_1_Net_FUSED_CELL_0-" (solid, pour order 719): 91.44,91.44 86.36,91.44 86.36,98.425 91.44,98.425
CELL_FEEDBACK.CELL11_FEEDBACK+ on Bottom "Polygon_1_Net_FUSED_CELL_0-" (solid, pour order 717): 85.725,91.44 80.645,91.44 80.645,98.425 85.725,98.425
CELL_FEEDBACK.CELL12_FEEDBACK+ on Bottom "Polygon_1_Net_FUSED_CELL_0-" (solid, pour order 715): 80.01,91.44 74.93,91.44 74.93,98.425 80.01,98.425
CELL_FEEDBACK.CELL13_FEEDBACK+ on Bottom "Polygon_1_Net_FUSED_CELL_0-" (solid, pour order 713): 74.295,91.44 69.215,91.44 69.215,98.425 74.295,98.425
CELL_FEEDBACK.CELL14_FEEDBACK+ on Bottom "Polygon_1_Net_FUSED_CELL_0-" (solid, pour order 711): 68.58,91.44 63.5,91.44 63.5,98.425 68.58,98.425
CELL_FEEDBACK.CELL15_FEEDBACK+ on Bottom "Polygon_1_Net_FUSED_CELL_0-" (solid, pour order 709): 62.865,91.44 57.785,91.44 57.785,98.425 62.865,98.425
CELL_FEEDBACK.CELL16_FEEDBACK+ on Bottom "Polygon_1_Net_FUSED_CELL_0-" (solid, pour order 707): 57.15,91.44 52.07,91.44 52.07,98.425 57.15,98.425
CELL_FEEDBACK.CELL17_FEEDBACK+ on Bottom "Polygon_1_Net_FUSED_CELL_0-" (solid, pour order 705): 51.435,91.44 46.355,91.44 46.355,98.425 51.435,98.425
FUSED_CELL.CELL_0+ on Bottom "Polygon_1_Net_N$4" (solid, pour order 703): 142.875,90.17 142.875,80.01 137.795,80.01 137.795,90.17
FUSED_CELL.CELL_1+ on Bottom "Polygon_1_Net_N$4" (solid, pour order 701): 137.16,90.17 137.16,80.01 132.08,80.01 132.08,90.17
FUSED_CELL.CELL_2+ on Bottom "Polygon_1_Net_N$4" (solid, pour order 699): 131.445,90.17 131.445,80.01 126.365,80.01 126.365,90.17
FUSED_CELL.CELL_3+ on Bottom "Polygon_1_Net_N$4" (solid, pour order 697): 125.73,90.17 125.73,80.01 120.65,80.01 120.65,90.17
FUSED_CELL.CELL_4+ on Bottom "Polygon_1_Net_N$4" (solid, pour order 695): 120.015,90.17 120.015,80.01 114.935,80.01 114.935,90.17
FUSED_CELL.CELL_5+ on Bottom "Polygon_1_Net_N$4" (solid, pour order 693): 114.303,90.17 114.303,80.01 109.223,80.01 109.223,90.17
FUSED_CELL.CELL_6+ on Bottom "Polygon_1_Net_N$4" (solid, pour order 691): 108.585,90.17 108.585,80.01 103.505,80.01 103.505,90.17
FUSED_CELL.CELL_7+ on Bottom "Polygon_1_Net_N$4" (solid, pour order 689): 102.87,90.17 102.87,80.01 97.79,80.01 97.79,90.17
FUSED_CELL.CELL_8+ on Bottom "Polygon_1_Net_N$4" (solid, pour order 687): 97.155,90.17 97.155,80.01 92.075,80.01 92.075,90.17
FUSED_CELL.CELL_9+ on Bottom "Polygon_1_Net_N$4" (solid, pour order 685): 91.44,90.17 91.44,80.01 86.36,80.01 86.36,90.17
FUSED_CELL.CELL_10+ on Bottom "Polygon_1_Net_N$4" (solid, pour order 683): 85.725,90.17 85.725,80.01 80.645,80.01 80.645,90.17
FUSED_CELL.CELL_11+ on Bottom "Polygon_1_Net_N$4" (solid, pour order 681): 80.01,90.17 80.01,80.01 74.93,80.01 74.93,90.17
FUSED_CELL.CELL_13+ on Bottom "Polygon_1_Net_N$4" (solid, pour order 677): 68.58,90.17 68.58,80.01 63.5,80.01 63.5,90.17
FUSED_CELL.CELL_14+ on Bottom "Polygon_1_Net_N$4" (solid, pour order 675): 62.865,90.17 62.865,80.01 57.785,80.01 57.785,90.17
FUSED_CELL.CELL_15+ on Bottom "Polygon_1_Net_N$4" (solid, pour order 673): 57.15,90.17 57.15,80.01 52.07,80.01 52.07,90.17
FUSED_CELL.CELL_16+ on Bottom "Polygon_1_Net_N$4" (solid, pour order 671): 51.435,90.17 51.435,80.01 46.355,80.01 46.355,90.17
CELL_FEEDBACK.CELL10_FEEDBACK+ on Bottom "Polygon_1_Net_CELL0_FEEDBACK+" (solid, pour order 669): 91.44,71.755 86.36,71.755 86.36,78.74 91.44,78.74
CELL_FEEDBACK.CELL15_FEEDBACK+ on Bottom "Polygon_1_Net_CELL0_FEEDBACK+" (solid, pour order 667): 62.865,71.755 57.785,71.755 57.785,78.74 62.865,78.74
CELL_FEEDBACK.CELL1_FEEDBACK+ on Bottom "Polygon_1_Net_CELL0_FEEDBACK+" (solid, pour order 665): 142.875,71.755 137.795,71.755 137.795,78.74 142.875,78.74
CELL_FEEDBACK.CELL2_FEEDBACK+ on Bottom "Polygon_1_Net_CELL0_FEEDBACK+" (solid, pour order 663): 137.16,71.755 132.08,71.755 132.08,78.74 137.16,78.74
CELL_FEEDBACK.CELL3_FEEDBACK+ on Bottom "Polygon_1_Net_CELL0_FEEDBACK+" (solid, pour order 661): 131.445,71.755 126.365,71.755 126.365,78.74 131.445,78.74
CELL_FEEDBACK.CELL4_FEEDBACK+ on Bottom "Polygon_1_Net_CELL0_FEEDBACK+" (solid, pour order 659): 125.73,71.755 120.65,71.755 120.65,78.74 125.73,78.74
CELL_FEEDBACK.CELL5_FEEDBACK+ on Bottom "Polygon_1_Net_CELL0_FEEDBACK+" (solid, pour order 657): 120.015,71.755 114.935,71.755 114.935,78.74 120.015,78.74
CELL_FEEDBACK.CELL6_FEEDBACK+ on Bottom "Polygon_1_Net_CELL0_FEEDBACK+" (solid, pour order 655): 114.303,71.755 109.223,71.755 109.223,78.74 114.303,78.74
CELL_FEEDBACK.CELL7_FEEDBACK+ on Bottom "Polygon_1_Net_CELL0_FEEDBACK+" (solid, pour order 653): 108.585,71.755 103.505,71.755 103.505,78.74 108.585,78.74
CELL_FEEDBACK.CELL8_FEEDBACK+ on Bottom "Polygon_1_Net_CELL0_FEEDBACK+" (solid, pour order 651): 102.873,71.755 97.793,71.755 97.793,78.74 102.873,78.74
CELL_FEEDBACK.CELL9_FEEDBACK+ on Bottom "Polygon_1_Net_CELL0_FEEDBACK+" (solid, pour order 649): 97.155,71.755 92.075,71.755 92.075,78.74 97.155,78.74
CELL_FEEDBACK.CELL11_FEEDBACK+ on Bottom "Polygon_1_Net_CELL0_FEEDBACK+" (solid, pour order 647): 85.725,71.755 80.645,71.755 80.645,78.74 85.725,78.74
CELL_FEEDBACK.CELL12_FEEDBACK+ on Bottom "Polygon_1_Net_CELL0_FEEDBACK+" (solid, pour order 645): 80.01,71.755 74.93,71.755 74.93,78.74 80.01,78.74
CELL_FEEDBACK.CELL14_FEEDBACK+ on Bottom "Polygon_1_Net_CELL0_FEEDBACK+" (solid, pour order 643): 68.58,71.755 63.5,71.755 63.5,78.74 68.58,78.74
CELL_FEEDBACK.CELL16_FEEDBACK+ on Bottom "Polygon_1_Net_CELL0_FEEDBACK+" (solid, pour order 641): 57.15,71.755 52.07,71.755 52.07,78.74 57.15,78.74
CELL_FEEDBACK.CELL17_FEEDBACK+ on Bottom "Polygon_1_Net_CELL0_FEEDBACK+" (solid, pour order 639): 51.435,71.755 46.355,71.755 46.355,78.74 51.435,78.74
CELL_FEEDBACK.CELL13_FEEDBACK+ on Bottom "Polygon_1_Net_CELL0_FEEDBACK+" (solid, pour order 637): 74.295,71.755 69.215,71.755 69.215,78.74 74.295,78.74
no net on Bottom Overlay "Polygon_21_NoNet" (solid): 155.81,42.906 153.02,42.906 153.019,43.478 154.233,43.478 154.234,44.416 154.689,44.416 154.69,43.478 155.353,43.48 155.354,44.463 155.809,44.462
no net on Bottom Overlay "Polygon_20_NoNet" (solid): 23 vertices, not listed, extent 153.018,44.822 155.135,46.041
no net on Bottom Overlay "Polygon_19_NoNet" (solid): 32 vertices, not listed, extent 152.973,46.176 154.282,47.125
no net on Bottom Overlay "Polygon_18_NoNet" (solid): 49 vertices, not listed, extent 152.988,46.396 155.132,48.038
no net on Bottom Overlay "Polygon_17_NoNet" (solid): 41 vertices, not listed, extent 152.974,48.425 155.087,50.32
no net on Bottom Overlay "Polygon_16_NoNet" (solid): 44 vertices, not listed, extent 153.018,50.848 155.133,52.736
no net on Bottom Overlay "Polygon_15_NoNet" (solid): 43 vertices, not listed, extent 153.019,53.261 156.012,55.155
no net on Bottom Overlay "Polygon_14_NoNet" (solid): 75 vertices, not listed, extent 152.973,55.467 155.136,57.625
no net on Bottom Overlay "Polygon_13_NoNet" (solid): 35 vertices, not listed, extent 153.017,57.736 156.061,59.186
no net on Bottom Overlay "Polygon_12_NoNet" (solid): 68 vertices, not listed, extent 152.969,59.32 155.123,61.253
no net on Bottom Overlay "Polygon_11_NoNet" (solid): 25 vertices, not listed, extent 152.964,61.551 155.193,62.9
no net on Bottom Overlay "Polygon_10_NoNet" (solid): 151.63,59.51 151.63,59.805 150.225,59.804 150.226,59.51
no net on Bottom Overlay "Polygon_9_NoNet" (solid): 151.63,60.143 151.63,60.427 150.225,60.427 150.227,60.144
no net on Bottom Overlay "Polygon_8_NoNet" (solid): 60 vertices, not listed, extent 150.202,60.717 151.653,61.604
no net on Bottom Overlay "Polygon_7_NoNet" (solid): 56 vertices, not listed, extent 150.225,61.871 151.634,62.839
no net on Bottom Overlay "Polygon_6_NoNet" (solid): 157.189,37.396 156.021,37.403 156.041,37.776 156.096,38.328 156.197,39.032 156.271,39.425 156.365,39.842 156.517,40.407 156.675,40.894 156.85,41.35 156.933,41.542 157.192,41.542
no net on Bottom Overlay "Polygon_5_NoNet" (solid): 35 vertices, not listed, extent 155.325,37.398 156.849,41.54
no net on Bottom Overlay "Polygon_4_NoNet" (solid): 35 vertices, not listed, extent 154.222,37.401 156.467,41.539
no net on Bottom Overlay "Polygon_3_NoNet" (solid): 31 vertices, not listed, extent 153.021,37.401 155.96,41.54
no net on Bottom Overlay "Polygon_2_NoNet" (solid): 50 vertices, not listed, extent 153.019,37.771 155.468,41.541
no net on Bottom Overlay "Polygon_1_NoNet" (solid): 24 vertices, not listed, extent 153.02,38.864 155.058,41.54
FUSED_VBAT- on FUSED_VBAT- "FUSED_VBAT--No Net" (solid, pour order 809): 160.02,0 160.02,100 34.925,100 34.925,69.215 5.08,69.215 5.08,32.067 17.145,32.067 17.145,25.717 52.07,25.717 52.07,13.97 55.88,13.97 55.88,0

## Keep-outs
Keep-Out Layer:
  region: 4.5,91 4.5,9 0,9 0,91
  region: 155,100 155,99 5,99 5,100
  region: 160,91 160,11.112 155.5,11.112 155.5,91
  lines w0.152: 0,1 ccw(c1,1) 1,0 159,0 ccw(c159,1) 160,1 160,99 ccw(c159,99) 159,100 1,100 ccw(c1,99) 0,99 0,1

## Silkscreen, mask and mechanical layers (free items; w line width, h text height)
Top Overlay:
  drawing of 80 lines, arcs and shapes, not listed
  text "galvanic    isolation" at 25.4,96.837 h1.02
  text "↯" at 34.608,94.615 h30.48
  text "isolating / DC/DC Converter" at 13.97,94.297 h1.52
  text "DANGER / high voltage / >60VDC" at 37.782,94.297 h1.52
  text "Passive Cell / Balancing" at 152.559,81.915 h1.52 r90
  text "foxBMS" at 3.492,77.787 h3.05 r90
  text "Analog / Multiplexers" at 12.065,69.85 h1.52
  text "FUSED_VBAT-" at 75.565,64.611 h1.02
  text "+5.0V_VREG_1" at 83.82,64.611 h1.02
  text "FUSED_VBAT-" at 129.54,64.611 h1.02
  text "+5.0V_VREG_0" at 137.636,64.611 h1.02
  text "Primary" at 133.826,61.436 h1.52
  text "Secondary" at 81.28,61.404 h1.52
  text "Fraunhofer IISB / foxBMS BMS-Slave 18-Cell V'.GlobalVersion'" at 152.082,58.737 h1.52 r90
  text "Creative Commons / Attribution 4.0" at 3.492,56.197 h1.27 r90
  text "+3.0V_VREF_2_0 / +3.0V_VREF_1_0 / SDA_0 /           SCL_0" at 151.13,54.673 h1.02
  text "DC/DC Converter" at 57.309,43.466 h1.52
  text "DC/DC Converter" at 112.331,43.307 h1.52
  text "Extension / Pin Headers" at 3.81,38.417 h1.52 r90
  text "Input Filter/Protection" at 157.321,29.654 h1.52 r90
  text "isoSPI / Transformers" at 2.921,26.543 h1.52
  text "↯" at 152.876,25.876 h30.48
  text "foxBMS" at 49.952,24.924 h5 r90
  text "galvanic / isolation" at 9.842,23.812 h1.02
  text "C_17+" at 115.57,23.812 h1.02 r90
  text "C_16+" at 117.475,23.812 h1.02 r90
  text "C_15+" at 119.38,23.812 h1.02 r90
  text "C_14+" at 121.285,23.812 h1.02 r90
  text "C_13+" at 123.19,23.812 h1.02 r90
  text "C_12+" at 125.095,23.812 h1.02 r90
  text "C_11+" at 127,23.812 h1.02 r90
  text "C_10+" at 128.905,23.812 h1.02 r90
  text "C_9+" at 130.81,23.812 h1.02 r90
  text "C_8+" at 132.715,23.812 h1.02 r90
  text "C_7+" at 134.62,23.812 h1.02 r90
  text "C_6+" at 136.525,23.812 h1.02 r90
  text "C_5+" at 138.43,23.812 h1.02 r90
  text "C_4+" at 140.335,23.812 h1.02 r90
  text "C_3+" at 142.24,23.812 h1.02 r90
  text "C_2+" at 144.145,23.812 h1.02 r90
  text "C_1+" at 146.05,23.812 h1.02 r90
  text "C_0+" at 147.955,23.812 h1.02 r90
  text "C_0-" at 149.86,23.812 h1.02 r90
  text "DANGER / high voltage" at 151.289,22.701 h1.52
  text "DC-" at 2.54,19.05 h1.02 r90
  text "DC-" at 4.127,19.05 h1.02 r90
  text "IN-" at 49.53,19.05 h1.02 r90
  text "OUT-" at 47.942,18.732 h1.02 r90
  text "Fuses / 0.25 A" at 116.046,18.574 h1.02 r90
  text "Fuses / 0.5 A" at 110.172,16.192 h1.02 r90
  text "DC+" at 2.54,15.875 h1.02 r90
  text "DC+" at 4.127,15.875 h1.02 r90
  text "IN+" at 49.53,15.875 h1.02 r90
  text "OUT+" at 47.942,15.24 h1.02 r90
  text "Input Fuses" at 157.321,13.621 h1.52 r90
  text "Fuse / 1.25 A" at 5.08,13.335 h1.02
Bottom Overlay:
  lines w0.203: 0.953,37.782 0.953,46.672 4.445,46.672 4.445,37.782 0.953,37.782 ; 13.97,12.383 16.51,12.383 16.51,23.812 13.97,23.812 13.97,12.383 ; 18.732,12.383 18.732,22.225 21.273,22.225 21.273,12.383 18.732,12.383 ; 26.035,12.383 26.035,28.258 28.575,28.258 28.575,12.383 26.035,12.383 ; 33.655,12.383 33.655,26.987 36.195,26.987 36.195,12.383 33.655,12.383 ; 41.275,12.383 41.275,26.352 43.815,26.352 43.815,12.383 41.275,12.383 ; 48.578,12.383 48.578,24.765 51.117,24.765 51.117,12.383 48.578,12.383 ; 60.325,12.383 75.565,12.383 75.565,17.462 71.755,17.462 64.135,17.462 63.182,17.462 60.325,17.462 60.325,12.383 ; 88.9,12.383 88.9,17.462 104.14,17.462 104.14,12.383 88.9,12.383 ; 126.682,12.383 126.682,16.51 134.938,16.51 134.938,12.383 126.682,12.383
  text "Extension / Pin Headers" at 1.587,38.405 h1.52 r270
  text "Temperature Sensors / Secondary" at 74.93,13.047 h1.52
  text "Temperature Sensors / Primary" at 103.505,13.047 h1.52
  text "DC Supply OUT" at 14.922,13.018 h1.52 r270
  text "DC Supply IN" at 19.685,13.018 h1.52 r270
  text "isoSPI OUT Secondary" at 26.987,13.018 h1.52 r270
  text "isoSPI IN Secondary" at 34.608,13.018 h1.52 r270
  text "isoSPI OUT Primary" at 42.227,13.018 h1.52 r270
  text "isoSPI IN Primary" at 49.53,13.018 h1.52 r270
  text "Cell Sense / Inputs" at 134.302,13.018 h1.52
Dimension:
  the board outline again, w0.152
